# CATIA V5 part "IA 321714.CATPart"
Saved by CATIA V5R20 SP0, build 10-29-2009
Part number: IA 321714
Revision: ANY
Definition: UNKNOWN
Nomenclature: IA 321714
Source: Unknown
Bounding box of the stored display mesh (mm): x -1.6 to 1.6, y -8.75 to 8.2, z -1.6 to 1.6
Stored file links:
  C:\Users\Utente\Desktop\IO LAVORO\3D X SITO CF\CUMSA\3D files FA\FA 063212-21\IA 321714.CATPart

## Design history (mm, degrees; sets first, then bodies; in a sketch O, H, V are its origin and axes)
Body1 "Cortar-Extruir4" (main body)
  Solid1: solid without history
